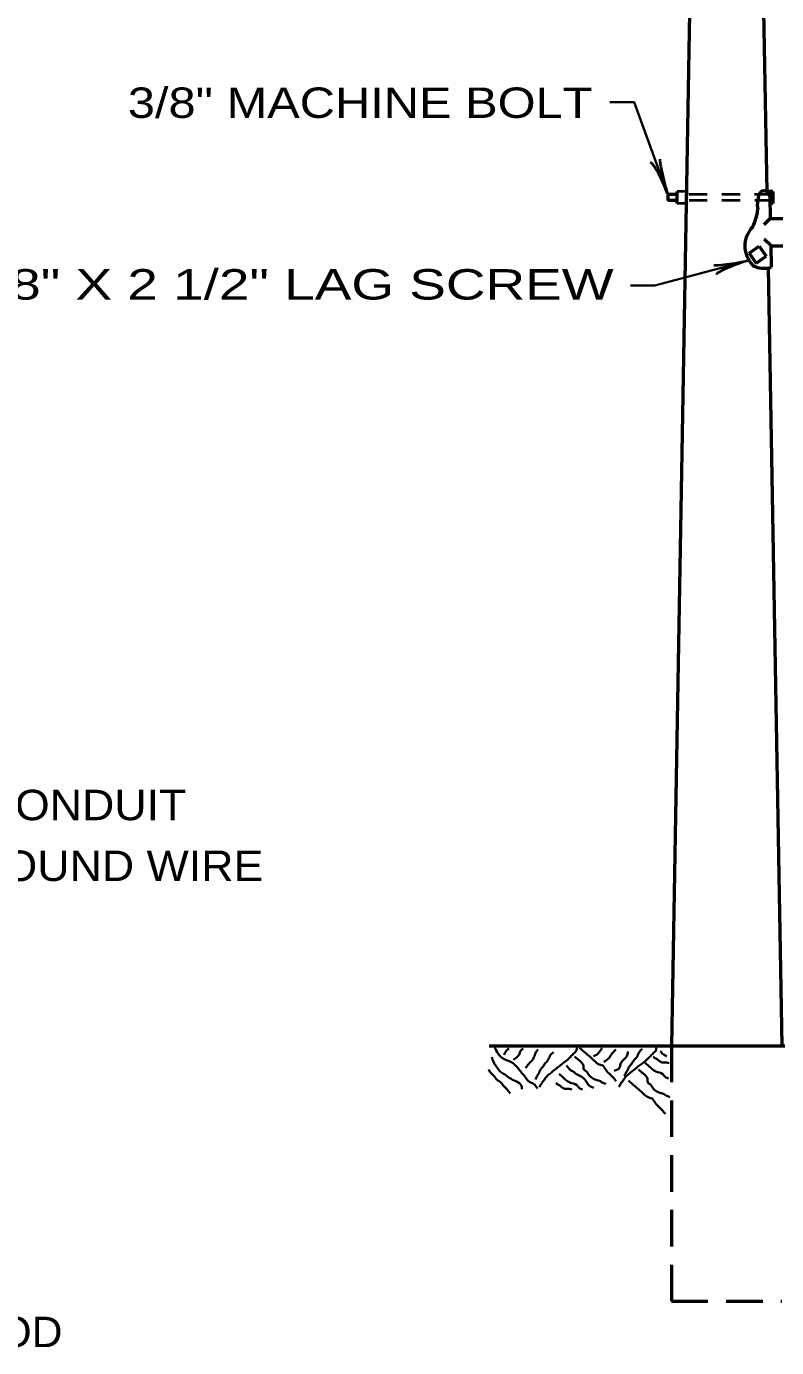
# Model space of a CAD drawing. Extents: x 12366 to 13046, y 9129 to 9570.
# Drawn here: x 12684.9 to 12746.6, y 9373 to 9481.6 of the extents above; entities that cross this region are included whole.
import ezdxf
from ezdxf.enums import TextEntityAlignment as Align

# ---------------------------------------------------------------- set-up
doc = ezdxf.new("R2010")
doc.units = 0
doc.linetypes.add('MEDIUM_DASHED', pattern=[4.5, 3, -1.5])
doc.linetypes.add('SHORT_DASHED', pattern=[2.7, 1.5, -1.2])
doc.layers.add('1', color=7, linetype='Continuous', lineweight=53)

msp = doc.modelspace()

# ---------------------------------------------------------------- linework, layer by layer
at = {"layer": '1'}
for p, q in [((12740.471, 9542.779), (12737.941, 9397.801)), ((12744.471, 9542.779), (12745.776, 9468.032)), ((12738.404, 9467.782), (12737.654, 9467.782)), ((12737.654, 9467.782), (12737.654, 9467.282)), ((12738.404, 9467.032), (12738.404, 9468.032)), ((12746.289, 9468.032), (12745.727, 9468.032)), ((12746.033, 9467.614), (12746.065, 9465.812)), ((12746.289, 9468.032), (12746.289, 9467.032)), ((12738.404, 9467.282), (12737.654, 9467.282)), ((12746.289, 9467.032), (12746.044, 9467.032)), ((12746.065, 9465.812), (12745.534, 9465.282)), ((12746.065, 9465.812), (12747.104, 9465.812)), ((12746.104, 9463.575), (12745.574, 9464.105)), ((12744.325, 9462.964), (12745.145, 9463.538)), ((12745.145, 9463.538), (12745.718, 9462.719)), ((12746.104, 9463.575), (12746.135, 9461.813)), ((12746.104, 9463.563), (12747.104, 9463.563)), ((12744.325, 9462.964), (12744.899, 9462.145)), ((12744.899, 9462.145), (12745.718, 9462.719)), ((12745.886, 9461.744), (12747.002, 9397.801)), ((12722.941, 9397.801), (12909.771, 9397.801))]:
    msp.add_line(p, q, dxfattribs=at)
at = {"layer": '1', "lineweight": 40}
for p, q in [((12739.162, 9468.032), (12738.404, 9468.032)), ((12739.154, 9467.032), (12738.404, 9467.032))]:
    msp.add_line(p, q, dxfattribs=at)
at = {"layer": '1', "linetype": 'SHORT_DASHED', "lineweight": 40}
for p, q in [((12746.28, 9467.782), (12739.162, 9467.782)), ((12746.289, 9467.282), (12739.154, 9467.282))]:
    msp.add_line(p, q, dxfattribs=at)
at = {"layer": '1', "linetype": 'MEDIUM_DASHED'}
for p, q in [((12737.941, 9397.801), (12737.941, 9376.801)), ((12737.941, 9376.801), (12747.002, 9376.801))]:
    msp.add_line(p, q, dxfattribs=at)
at = {"layer": '1', "lineweight": 35}
for points in [[(12737.617, 9467.842), (12734.881, 9475.36), (12732.881, 9475.36)], [(12744.31, 9462.356), (12736.583, 9460.285), (12734.583, 9460.285)]]:
    msp.add_lwpolyline(points, dxfattribs=at)
at = {"layer": '1'}
for centre, radius, start, end in [((12747.148, 9466.963), 2.151, 151.6071, 191.23066), ((12745.534, 9467.569), 0.501, 5.14198, 123.76222), ((12741.078, 9466.97), 3.982, 331.99837, 353.85569), ((12746.226, 9463.546), 2.254, 136.38146, 225.27926), ((12745.53, 9463.512), 1.803, 240.4205, 289.57853)]:
    msp.add_arc(centre, radius, start, end, dxfattribs=at)
at = {"layer": '1', "lineweight": 40}
for centre, major_axis, ratio, start_param, end_param in [((12737.433, 9468.968), (-0.436, 1.711), 0.07063, 6.2823074, 8.5597026), ((12736.984, 9468.773), (0.757, -1.625), 0.122415, 0.8963533, 3.1415927), ((12743.173, 9462.27), (-1.742, -0.285), 0.07063, 6.2823074, 8.5597026), ((12743.328, 9461.806), (1.684, 0.613), 0.122415, 0.8963533, 3.1415927)]:
    msp.add_ellipse(centre, major_axis=major_axis, ratio=ratio, start_param=start_param, end_param=end_param, dxfattribs=at)
at = {"layer": '1', "lineweight": 35}
for points in [[(12723.181, 9396.86), (12723.309, 9396.476), (12723.565, 9396.06), (12723.885, 9395.644), (12724.205, 9395.452), (12724.749, 9395.068), (12725.613, 9394.493), (12725.645, 9394.237)], [(12723.405, 9397.667), (12724.045, 9396.771), (12724.877, 9396.388), (12725.389, 9395.876), (12725.645, 9395.556), (12725.965, 9395.172), (12726.22, 9394.852), (12726.604, 9394.66), (12726.924, 9394.276)], [(12724.557, 9397.596), (12724.461, 9397.468), (12724.429, 9397.468), (12724.365, 9397.404), (12724.205, 9397.116), (12724.173, 9397.052)], [(12725.741, 9397.564), (12725.549, 9397.404), (12725.485, 9397.244), (12725.421, 9397.052), (12725.293, 9396.924), (12725.229, 9396.86), (12724.941, 9396.636)], [(12726.988, 9397.468), (12726.796, 9397.276), (12726.668, 9396.956), (12726.508, 9396.636), (12726.156, 9396.252), (12726.029, 9396.06), (12725.965, 9395.964)], [(12728.236, 9397.276), (12727.948, 9396.956), (12727.788, 9396.604), (12727.532, 9396.316), (12727.34, 9396.028), (12727.148, 9395.804), (12727.052, 9395.58), (12726.924, 9395.356), (12726.764, 9395.036)], [(12730.155, 9397.667), (12730.155, 9397.539), (12730.091, 9397.347), (12729.963, 9397.219), (12729.835, 9397.091), (12729.579, 9396.835), (12729.387, 9396.644), (12728.811, 9396.196), (12728.492, 9395.94), (12727.852, 9395.428), (12727.596, 9395.172), (12727.468, 9394.98), (12727.276, 9394.724), (12727.084, 9394.404)], [(12729.963, 9396.892), (12730.155, 9396.764), (12730.347, 9396.604), (12730.699, 9396.156), (12730.731, 9395.868), (12730.987, 9395.644), (12731.083, 9395.484), (12731.723, 9395.004), (12732.106, 9394.877), (12732.202, 9394.812), (12732.554, 9394.653)], [(12730.379, 9397.635), (12730.891, 9397.187), (12731.339, 9396.803), (12732.106, 9396.228), (12732.298, 9396.164), (12732.49, 9395.908), (12732.81, 9395.524), (12733.194, 9395.14), (12733.386, 9394.884)], [(12731.531, 9396.924), (12731.978, 9397.244), (12732.074, 9397.372), (12732.234, 9397.596)], [(12732.394, 9396.476), (12732.746, 9396.732), (12732.97, 9397.052), (12733.034, 9397.148), (12733.162, 9397.276), (12733.354, 9397.5)], [(12733.226, 9395.74), (12733.674, 9395.996), (12733.738, 9396.284), (12734.154, 9396.796), (12734.282, 9396.956), (12734.346, 9397.212), (12734.378, 9397.34)], [(12736.693, 9397.688), (12736.693, 9397.56), (12736.629, 9397.368), (12736.502, 9397.24), (12736.374, 9397.112), (12736.118, 9396.856), (12735.926, 9396.664), (12735.35, 9396.216), (12735.03, 9395.96), (12734.39, 9395.449), (12734.134, 9395.193), (12734.006, 9395.001), (12733.815, 9394.745), (12733.623, 9394.425)], [(12735.537, 9397.544), (12735.249, 9397.224), (12735.09, 9396.872), (12734.834, 9396.584), (12734.642, 9396.296), (12734.45, 9396.072), (12734.354, 9395.848), (12734.226, 9395.624), (12734.066, 9395.305)], [(12736.431, 9396.882), (12736.654, 9396.754), (12737.07, 9396.466), (12737.134, 9396.434), (12737.326, 9396.434), (12737.742, 9396.37)], [(12737.018, 9397.323), (12737.146, 9397.227), (12737.146, 9397.195), (12737.21, 9397.131), (12737.498, 9396.971), (12737.562, 9396.939)], [(12722.926, 9395.836), (12723.053, 9395.612), (12723.309, 9395.356), (12723.629, 9394.972), (12723.917, 9394.78), (12724.173, 9394.461), (12724.429, 9394.205), (12724.685, 9393.885)], [(12729.323, 9396.188), (12729.803, 9395.708), (12729.899, 9395.676), (12729.995, 9395.58), (12730.411, 9395.324), (12730.923, 9394.877), (12731.083, 9394.621), (12731.563, 9394.333)], [(12735.223, 9395.819), (12735.415, 9395.691), (12735.607, 9395.531), (12735.958, 9395.083), (12735.99, 9394.796), (12736.246, 9394.572), (12736.342, 9394.412), (12736.982, 9393.932), (12737.366, 9393.804), (12737.462, 9393.74), (12737.814, 9393.58)], [(12735.79, 9396.392), (12736.206, 9396.008), (12736.366, 9395.88), (12736.654, 9395.688), (12737.23, 9395.464), (12737.422, 9395.24), (12737.71, 9395.112)], [(12728.428, 9394.717), (12728.652, 9394.589), (12729.067, 9394.301), (12729.131, 9394.269), (12729.323, 9394.269), (12729.739, 9394.205)], [(12728.716, 9395.484), (12729.131, 9395.1), (12729.291, 9394.972), (12729.579, 9394.78), (12730.155, 9394.557), (12730.347, 9394.333), (12730.635, 9394.205)], [(12734.422, 9394.933), (12734.933, 9394.485), (12735.381, 9394.101), (12736.149, 9393.526), (12736.341, 9393.462), (12736.533, 9393.206), (12736.853, 9392.822), (12737.237, 9392.438), (12737.429, 9392.182)]]:
    msp.add_spline(points, degree=3, dxfattribs=at)

# ---------------------------------------------------------------- texts
at = {"layer": '1'}
for s, width, p in [('3/8" MACHINE BOLT', 1.2, (12731.451, 9474.074)), ('3/8" X 2 1/2" LAG SCREW', 1.35, (12733.184, 9459.141))]:
    msp.add_text(s, height=2.5, dxfattribs=dict(at, width=width)).set_placement(p, align=Align.RIGHT)
for s, width, p in [('STEEL CONDUIT', 1.1, (12668.635, 9416.343)), ('FOR GROUND WIRE', 1.1, (12668.635, 9411.343)), ('GROUND ROD', 1.05, (12663.497, 9373.023))]:
    msp.add_text(s, height=2.5, dxfattribs=dict(at, width=width)).set_placement(p)

doc.saveas('drawing.dxf')
